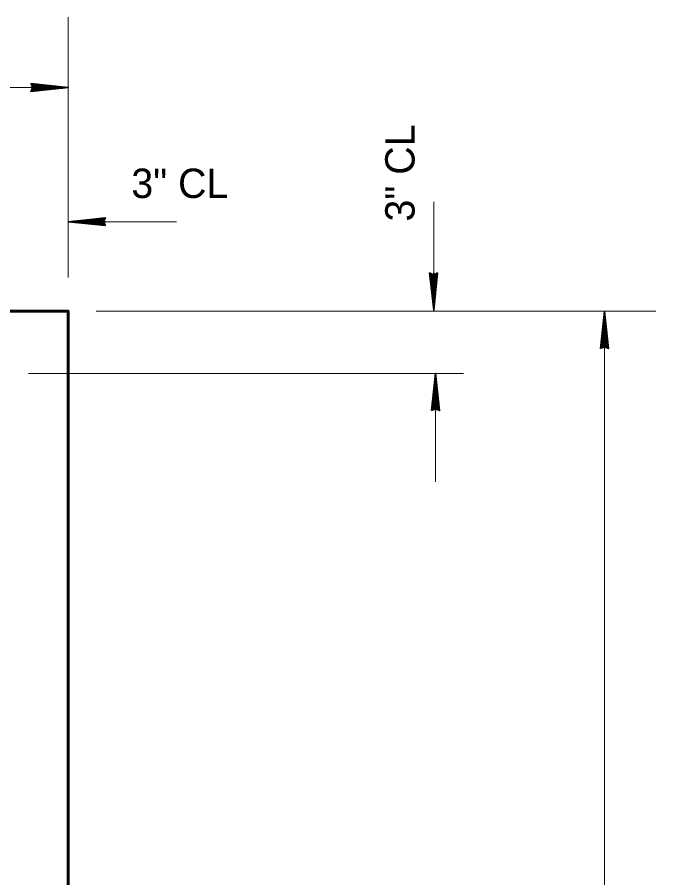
# Model space of a CAD drawing. Extents: x 6.34 to 9.53, y -1.46 to 0.53.
# Drawn here: x 7.9456 to 8.1267, y -0.5501 to -0.3062 of the extents above; entities that cross this region are included whole.
import ezdxf

# ---------------------------------------------------------------- set-up
doc = ezdxf.new("R2010")
doc.units = 0
doc.header["$LTSCALE"] = 0.0033
doc.layers.add('1', color=7, linetype='Continuous', lineweight=40)

msp = doc.modelspace()

# ---------------------------------------------------------------- linework, layer by layer
at = {"layer": '1', "lineweight": 13}
for p, q in [((7.960083, -0.38), (7.960083, -0.306167)), ((7.793667, -0.326083), (7.960083, -0.326083)), ((8.06375, -0.379333), (8.06375, -0.3585)), ((7.97, -0.364167), (7.990833, -0.364167)), ((7.968, -0.3895), (8.12675, -0.3895)), ((8.112167, -0.805333), (8.112167, -0.389583)), ((7.960083, -0.474583), (7.960083, -0.40175)), ((7.948833, -0.407167), (8.07225, -0.407167)), ((8.06425, -0.437833), (8.06425, -0.417))]:
    msp.add_line(p, q, dxfattribs=at)
at = {"layer": '1', "lineweight": 35}
for p, q in [((7.9495, -0.326083), (7.960083, -0.326083)), ((7.949667, -0.32675), (7.957, -0.326)), ((7.94975, -0.325083), (7.957583, -0.326)), ((7.94975, -0.325083), (7.957583, -0.326)), ((7.94975, -0.325167), (7.957583, -0.326)), ((7.94975, -0.32525), (7.957583, -0.326083)), ((7.94975, -0.32525), (7.957583, -0.32625)), ((7.94975, -0.326917), (7.957083, -0.326083)), ((7.94975, -0.327), (7.957083, -0.32625)), ((7.94975, -0.327167), (7.957083, -0.326333)), ((7.970417, -0.363083), (7.963083, -0.363917)), ((7.970417, -0.36325), (7.963083, -0.364)), ((7.970417, -0.363333), (7.963083, -0.364167)), ((7.970667, -0.364167), (7.960083, -0.364167)), ((7.970417, -0.365), (7.962583, -0.364)), ((7.970417, -0.365), (7.962583, -0.364167)), ((7.970417, -0.365167), (7.962583, -0.36425)), ((7.970417, -0.365167), (7.962583, -0.36425)), ((7.970417, -0.365083), (7.962583, -0.36425)), ((7.9705, -0.3635), (7.963167, -0.36425)), ((8.062667, -0.378917), (8.0635, -0.38625)), ((8.062833, -0.378917), (8.063583, -0.38625)), ((8.062917, -0.378917), (8.06375, -0.38625)), ((8.063083, -0.378833), (8.063833, -0.386167)), ((8.064583, -0.378917), (8.063583, -0.38675)), ((8.06375, -0.378667), (8.06375, -0.38925)), ((8.064583, -0.378917), (8.06375, -0.38675)), ((8.06475, -0.378917), (8.063833, -0.38675)), ((8.06475, -0.378917), (8.063833, -0.38675)), ((8.064667, -0.378917), (8.063833, -0.38675)), ((8.112167, -0.400083), (8.112167, -0.3895)), ((8.111167, -0.399833), (8.112083, -0.392)), ((8.111167, -0.399833), (8.112083, -0.392)), ((8.11125, -0.399833), (8.112083, -0.392)), ((8.111333, -0.399833), (8.112167, -0.392)), ((8.111333, -0.399833), (8.112333, -0.392)), ((8.112833, -0.399917), (8.112083, -0.392583)), ((8.113, -0.399833), (8.112167, -0.3925)), ((8.113083, -0.399833), (8.112333, -0.3925)), ((8.11325, -0.399833), (8.112417, -0.3925)), ((8.06425, -0.417667), (8.06425, -0.407083)), ((8.06325, -0.417417), (8.064167, -0.409583)), ((8.06325, -0.417417), (8.064167, -0.409583)), ((8.063333, -0.417417), (8.064167, -0.409583)), ((8.063417, -0.417417), (8.06425, -0.409583)), ((8.063417, -0.417417), (8.064417, -0.409583)), ((8.064917, -0.4175), (8.064167, -0.410167)), ((8.065083, -0.417417), (8.06425, -0.410083)), ((8.065167, -0.417417), (8.064417, -0.410083)), ((8.065333, -0.417417), (8.0645, -0.410083))]:
    msp.add_line(p, q, dxfattribs=at)
for points in [[(7.9495, -0.325), (7.960083, -0.326083), (7.9495, -0.32725), (7.950083, -0.326083)], [(7.95025, -0.326), (7.954917, -0.325917), (7.954917, -0.326), (7.954, -0.326), (7.95025, -0.325917), (7.95325, -0.325833), (7.950083, -0.32575), (7.952333, -0.325667), (7.950083, -0.325583), (7.953583, -0.325833), (7.95825, -0.326), (7.957333, -0.32625), (7.958583, -0.32625), (7.95025, -0.32625), (7.952667, -0.326417), (7.950083, -0.326417), (7.955417, -0.326), (7.950083, -0.326667)], [(7.970667, -0.36525), (7.960083, -0.364167), (7.970667, -0.363), (7.970083, -0.364167)], [(7.969917, -0.36425), (7.96525, -0.364333), (7.96525, -0.36425), (7.966167, -0.36425), (7.969917, -0.364333), (7.966917, -0.364417), (7.970083, -0.3645), (7.967833, -0.364583), (7.970083, -0.364667), (7.966583, -0.364417), (7.961917, -0.36425), (7.962833, -0.364), (7.961583, -0.364), (7.969917, -0.364), (7.9675, -0.363833), (7.970083, -0.363833), (7.96475, -0.36425), (7.970083, -0.363583)], [(8.064833, -0.378667), (8.06375, -0.38925), (8.062583, -0.378667), (8.06375, -0.37925)], [(8.063833, -0.379417), (8.063917, -0.384083), (8.063833, -0.384083), (8.063833, -0.383167), (8.063917, -0.379417), (8.064, -0.382417), (8.064083, -0.37925), (8.064167, -0.3815), (8.06425, -0.37925), (8.064, -0.38275), (8.063833, -0.387417), (8.063583, -0.3865), (8.063583, -0.38775), (8.063583, -0.379417), (8.063417, -0.381833), (8.063417, -0.37925), (8.063833, -0.384583), (8.063167, -0.37925)], [(8.111083, -0.400083), (8.112167, -0.3895), (8.113333, -0.400083), (8.112167, -0.3995)], [(8.112083, -0.399333), (8.112, -0.394667), (8.112083, -0.394667), (8.112083, -0.395583), (8.112, -0.399333), (8.111917, -0.396333), (8.111833, -0.3995), (8.11175, -0.39725), (8.111667, -0.3995), (8.111917, -0.396), (8.112083, -0.391333), (8.112333, -0.39225), (8.112333, -0.391), (8.112333, -0.399333), (8.1125, -0.396917), (8.1125, -0.3995), (8.112083, -0.394167), (8.11275, -0.3995)], [(8.063167, -0.417667), (8.06425, -0.407083), (8.065417, -0.417667), (8.06425, -0.417083)], [(8.064167, -0.416917), (8.064083, -0.41225), (8.064167, -0.41225), (8.064167, -0.413167), (8.064083, -0.416917), (8.064, -0.413917), (8.063917, -0.417083), (8.063833, -0.414833), (8.06375, -0.417083), (8.064, -0.413583), (8.064167, -0.408917), (8.064417, -0.409833), (8.064417, -0.408583), (8.064417, -0.416917), (8.064583, -0.4145), (8.064583, -0.417083), (8.064167, -0.41175), (8.064833, -0.417083)]]:
    msp.add_lwpolyline(points, close=True, dxfattribs=at)
for points in [[(7.95025, -0.326), (7.949833, -0.32525), (7.950083, -0.3255), (7.95025, -0.325833), (7.9505, -0.32575), (7.950333, -0.325417), (7.950167, -0.326167), (7.95, -0.326667), (7.94975, -0.327083)], [(7.969917, -0.36425), (7.970333, -0.365), (7.970083, -0.36475), (7.969917, -0.364417), (7.969667, -0.3645), (7.969833, -0.364833), (7.97, -0.364083), (7.970167, -0.363583), (7.970417, -0.363167)], [(8.063833, -0.379417), (8.064583, -0.379), (8.064333, -0.37925), (8.064, -0.379417), (8.064083, -0.379667), (8.064417, -0.3795), (8.063667, -0.379333), (8.063167, -0.379167), (8.06275, -0.378917)], [(8.112083, -0.399333), (8.111333, -0.39975), (8.111583, -0.3995), (8.111917, -0.399333), (8.111833, -0.399083), (8.1115, -0.39925), (8.11225, -0.399417), (8.11275, -0.399583), (8.113167, -0.399833)], [(8.064167, -0.416917), (8.063417, -0.417333), (8.063667, -0.417083), (8.064, -0.416917), (8.063917, -0.416667), (8.063583, -0.416833), (8.064333, -0.417), (8.064833, -0.417167), (8.06525, -0.417417)]]:
    msp.add_lwpolyline(points, dxfattribs=at)
at = {"layer": '1', "lineweight": 60}
msp.add_lwpolyline([(7.710083, -0.722833), (7.793417, -0.722833), (7.793417, -0.3895), (7.960083, -0.3895), (7.960083, -0.722833), (8.043417, -0.722833)], dxfattribs=at)

# ---------------------------------------------------------------- texts
at = {"layer": '1'}
msp.add_text('3" CL', height=0.008334, rotation=90, dxfattribs=at).set_placement((8.058333, -0.364083))
msp.add_text('3" CL', height=0.008334, dxfattribs=at).set_placement((7.978, -0.357417))

doc.saveas('drawing.dxf')
